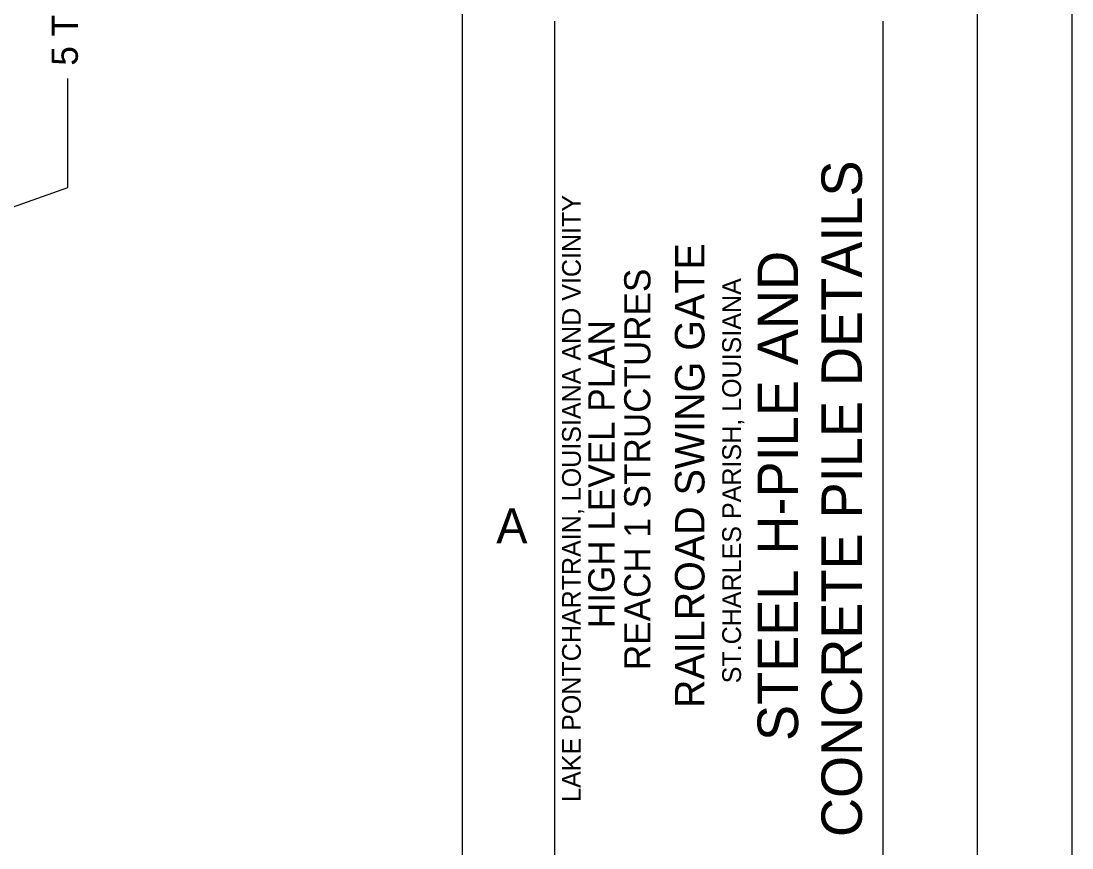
# Model space of a CAD drawing. Extents: x 22369.62 to 22373.29, y 22366.31 to 22369.14.
# Drawn here: x 22372.8194 to 22373.2867, y 22366.5497 to 22366.9176 of the extents above; entities that cross this region are included whole.
import ezdxf

# ---------------------------------------------------------------- set-up
doc = ezdxf.new("R2010")
doc.units = 0
for name, color, linetype in [('Level 1', 7, 'Continuous'), ('Level 10', 7, 'Continuous'), ('Level 2', 7, 'Continuous'), ('Level 3', 7, 'Continuous'), ('Level 4', 7, 'Continuous'), ('Level 7', 7, 'Continuous'), ('Level 9', 7, 'Continuous')]:
    doc.layers.add(name, color=color, linetype=linetype)

msp = doc.modelspace()

# ---------------------------------------------------------------- linework, layer by layer
at = {"layer": 'Level 1'}
msp.add_lwpolyline([(22369.6213, 22369.14218), (22373.2867, 22369.14218), (22373.2867, 22366.30818), (22369.6213, 22366.30818)], close=True, dxfattribs=at)
for points in [[(22373.0567, 22366.5318), (22373.0567, 22366.91755)], [(22373.2027, 22366.5318), (22373.2027, 22366.91755)]]:
    msp.add_lwpolyline(points, dxfattribs=at)
at = {"layer": 'Level 3'}
for p, q in [((22372.84022, 22366.84351), (22372.84022, 22366.89198)), ((22372.79641, 22366.82798), (22372.84022, 22366.84351))]:
    msp.add_line(p, q, dxfattribs=at)
at = {"layer": 'Level 9'}
msp.add_line((22373.2447, 22366.35017), (22373.2447, 22369.10017), dxfattribs=at)
msp.add_lwpolyline([(22373.0157, 22366.35017), (22373.0157, 22369.10017)], dxfattribs=at)

# ---------------------------------------------------------------- texts
at = {"layer": 'Level 1'}
msp.add_text('A', height=0.01561, dxfattribs=at).set_placement((22373.0307, 22366.68518))
at = {"layer": 'Level 10'}
msp.add_text('RAILROAD SWING GATE', height=0.0131249, rotation=90, dxfattribs=at).set_placement((22373.1233, 22366.61194))
at = {"layer": 'Level 2'}
for s, p in [('LAKE PONTCHARTRAIN, LOUISIANA AND VICINITY', (22373.06832, 22366.5702)), ('ST.CHARLES PARISH, LOUISIANA', (22373.13954, 22366.62295))]:
    msp.add_text(s, height=0.0083332, rotation=90, dxfattribs=at).set_placement(p)
at = {"layer": 'Level 3'}
for s, p in [(' CONCRETE PILE DETAILS', (22373.19331, 22366.54788)), ('STEEL H-PILE AND', (22373.16491, 22366.59728))]:
    msp.add_text(s, height=0.0179999, rotation=90, dxfattribs=at).set_placement(p)
at = {"layer": 'Level 4'}
msp.add_text("5 TURNS AT 1'' = 5''", height=0.0116667, rotation=90, dxfattribs=at).set_placement((22372.8447, 22366.89769))
at = {"layer": 'Level 7'}
for s, p in [('REACH 1 STRUCTURES', (22373.09927, 22366.62883)), ('HIGH LEVEL PLAN', (22373.08331, 22366.64753))]:
    msp.add_text(s, height=0.0116666, rotation=90, dxfattribs=at).set_placement(p)

doc.saveas('drawing.dxf')
